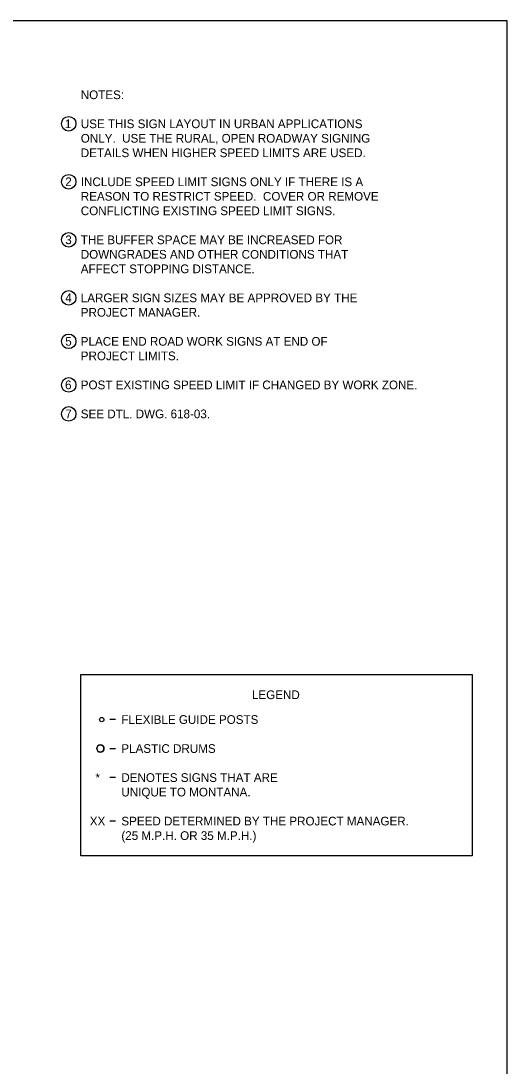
# Model space of a CAD drawing. Extents: x 49991.4 to 50021, y 49987.6 to 50011.4.
# Drawn here: x 50005.26 to 50008.61, y 50004.06 to 50011.26 of the extents above; entities that cross this region are included whole.
import ezdxf

# ---------------------------------------------------------------- set-up
doc = ezdxf.new("R2010")
doc.units = 0
doc.layers.add('Level 1', color=7, linetype='Continuous')
doc.layers.add('Level 2', color=7, linetype='Continuous')

msp = doc.modelspace()

# ---------------------------------------------------------------- linework, layer by layer
at = {"layer": 'Level 1'}
msp.add_lwpolyline([(50008.6146, 50011.2628), (50000.3356, 50011.2628), (50000.3356, 50000.0624), (50008.6146, 50000.0624)], close=True, dxfattribs=at)
for centre, radius in [((50005.8179, 50006.4464), 0.015), ((50005.8079, 50006.2464), 0.025)]:
    msp.add_circle(centre, radius, dxfattribs=at)
for start, end in [(360, 180), (180, 0)]:
    msp.add_arc((50005.8079, 50006.2464), 0.025, start, end, dxfattribs=at)
at = {"layer": 'Level 2'}
for p, q in [((50005.6729, 50005.5064), (50005.6729, 50006.7573)), ((50005.9129, 50006.4464), (50005.8729, 50006.4464)), ((50005.8729, 50006.2464), (50005.9129, 50006.2464)), ((50005.9129, 50006.0464), (50005.8729, 50006.0464)), ((50005.9129, 50005.7464), (50005.8729, 50005.7464)), ((50008.3724, 50005.5064), (50005.6729, 50005.5064))]:
    msp.add_line(p, q, dxfattribs=at)
msp.add_lwpolyline([(50005.6729, 50006.7573), (50008.3724, 50006.7573), (50008.3724, 50005.5064)], dxfattribs=at)
for centre in [(50005.5897, 50010.5536), (50005.5897, 50010.1536), (50005.5897, 50009.7536), (50005.5897, 50009.3536), (50005.5897, 50009.0536), (50005.5897, 50008.7536), (50005.5897, 50008.5536)]:
    msp.add_circle(centre, 0.0501, dxfattribs=at)

# ---------------------------------------------------------------- texts
for s, p in [('NOTES:', (50005.6729, 50010.7235)), ('1', (50005.5634, 50010.5235)), ('USE THIS SIGN LAYOUT IN URBAN APPLICATIONS', (50005.6729, 50010.5235)), ('ONLY.  USE THE RURAL, OPEN ROADWAY SIGNING', (50005.6729, 50010.4235)), ('DETAILS WHEN HIGHER SPEED LIMITS ARE USED.', (50005.6729, 50010.3235)), ('2', (50005.5659, 50010.1236)), ('INCLUDE SPEED LIMIT SIGNS ONLY IF THERE IS A', (50005.6729, 50010.1235)), ('REASON TO RESTRICT SPEED.  COVER OR REMOVE', (50005.6729, 50010.0235)), ('CONFLICTING EXISTING SPEED LIMIT SIGNS.', (50005.6729, 50009.9235)), ('3', (50005.5659, 50009.7236)), ('THE BUFFER SPACE MAY BE INCREASED FOR', (50005.6729, 50009.7235)), ('DOWNGRADES AND OTHER CONDITIONS THAT ', (50005.6729, 50009.6235)), ('AFFECT STOPPING DISTANCE.', (50005.6729, 50009.5235)), ('4', (50005.5659, 50009.3236)), ('LARGER SIGN SIZES MAY BE APPROVED BY THE', (50005.6729, 50009.3235)), ('PROJECT MANAGER.', (50005.6729, 50009.2235)), ('5', (50005.5659, 50009.0236)), ('PLACE END ROAD WORK SIGNS AT END OF', (50005.6729, 50009.0235)), ('PROJECT LIMITS.', (50005.6729, 50008.9235)), ('6', (50005.5643, 50008.7236)), ('POST EXISTING SPEED LIMIT IF CHANGED BY WORK ZONE.', (50005.6729, 50008.7235)), ('7', (50005.5659, 50008.5236)), ('SEE DTL. DWG. 618-03.', (50005.6729, 50008.5235)), ('LEGEND', (50006.854, 50006.5873)), ('FLEXIBLE GUIDE POSTS', (50005.9529, 50006.4164)), ('PLASTIC DRUMS', (50005.9529, 50006.2164)), ('*', (50005.7743, 50006.0164)), ('DENOTES SIGNS THAT ARE', (50005.9529, 50006.0164)), ('UNIQUE TO MONTANA.', (50005.9529, 50005.9164)), ('XX', (50005.7351, 50005.7164)), ('SPEED DETERMINED BY THE PROJECT MANAGER.', (50005.9529, 50005.7164)), ('(25 M.P.H. OR 35 M.P.H.)', (50005.9529, 50005.6164))]:
    msp.add_text(s, height=0.06, dxfattribs=at).set_placement(p)

doc.saveas('drawing.dxf')
